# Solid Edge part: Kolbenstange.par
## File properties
Username: bmolnar
Dokumentum tartalom típus: 0
Author: bmolnar
Last saved by: bmolnar
Revision: 100
Sűrűség: 0,000 kg/m^3
Pontosság: 0,990
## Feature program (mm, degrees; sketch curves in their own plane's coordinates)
base feature "unnamed BaseFeature 1"
sketch for "unnamed Protrusion 1" plane through (39.2, 0, 0) normal (1, 0, 0) x-axis (0, 1, 0)
  circle centre (0, 0) radius 50
extrude "unnamed Protrusion 1" add finite 23.3 along +normal
sketch for "Kihúzás_3" plane through (39.2, 0, 0) normal (1, 0, 0) x-axis (0, 1, 0)
  circle centre (0, 0) radius 50
extrude "Kihúzás_3" add finite 4.7 along -normal
sketch for "Furat_1" plane through (-495, 0, 0) normal (-1, 0, 0) x-axis (0, -1, 0)
  hole centre (0, 0) bore radius 5.053
hole "Furat_1" nominal diameter 12 finite  ThreadDepth = 22 mm
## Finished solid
Body 1: solid body, 14 faces, 20 edges, 8 vertices.
  Faces by surface: plane 8, cylinder 4, cone 1, torus 1
  Edges by curve: circle 10, line 6, ellipse 2, intersection 2
Bounding box of the edges (mm; curved faces can reach further): 557.545 x 100.000 x 100.000, from (-495.0451, -50, -50) to (62.5, 50, 50).
Cylindrical faces by radius (mm): R5.053 x2, R12.5 x1, R50 x1
Conical faces (half-angle, radius in mm at the cone's reference point): 45 deg R5.05 x1
Toroidal faces (ring radius, tube radius in mm): R10.7 r1.8 x1
Planar faces by outward normal: +x 1, +y 1, -x 3, -y 1, oblique 2
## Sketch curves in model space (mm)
circle centre (39.2, 0, 0) radius 50
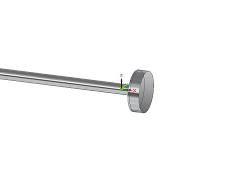
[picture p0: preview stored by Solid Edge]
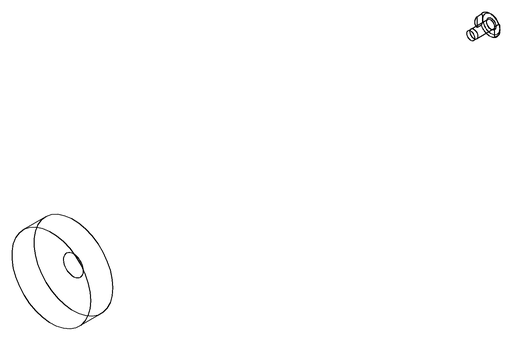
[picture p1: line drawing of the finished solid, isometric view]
